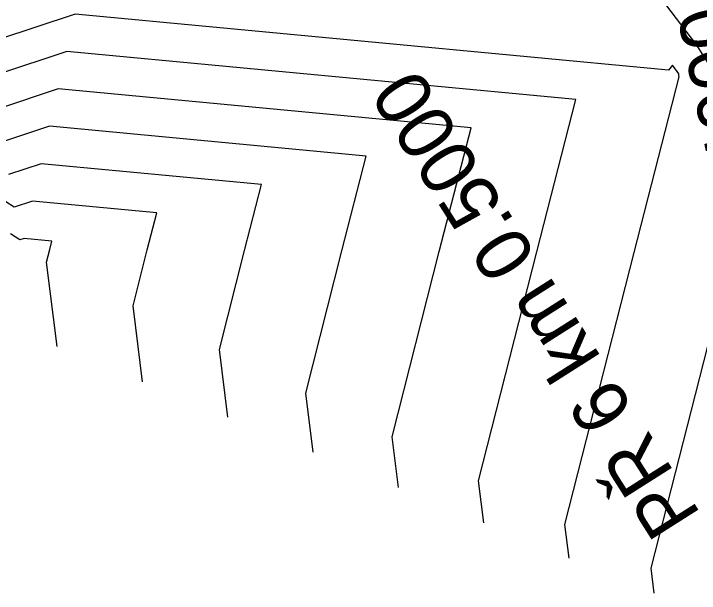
# Model space of a CAD drawing. Extents: x -549394 to -546608, y -1037055 to -1033629.
# Drawn here: x -548066.1 to -547954.3, y -1035778.1 to -1035683.5 of the extents above; entities that cross this region are included whole.
import ezdxf

# ---------------------------------------------------------------- set-up
doc = ezdxf.new("R2010")
doc.units = 0
for name, color, linetype in [('hlavni_vrst', 7, 'Continuous'), ('norm_vrst', 7, 'Continuous'), ('x_popis_pricne_rezy_C11', 7, 'Continuous')]:
    doc.layers.add(name, color=color, linetype=linetype)

msp = doc.modelspace()

# ---------------------------------------------------------------- linework, layer by layer
at = {"layer": 'hlavni_vrst'}
for p, q in [((-548056.05, -1035683.58), (-548070.72, -1035688.47)), ((-547959.3, -1035692.74), (-548056.05, -1035683.58)), ((-547958.65, -1035691.93), (-547959.3, -1035692.74)), ((-547957.89, -1035692.94), (-547958.65, -1035691.93)), ((-547964.92, -1035722.49), (-547957.57, -1035693.82)), ((-547957.63, -1035693.36), (-547957.89, -1035692.94)), ((-547957.61, -1035693.71), (-547957.63, -1035693.36)), ((-547957.57, -1035693.82), (-547957.61, -1035693.71)), ((-548066.01, -1035715.11), (-548072.95, -1035710.68)), ((-548063, -1035714.11), (-548066.01, -1035715.11)), ((-548042.75, -1035716.02), (-548063, -1035714.11)), ((-548044.31, -1035722.08), (-548042.75, -1035716.02)), ((-548046.62, -1035731.19), (-548044.31, -1035722.08)), ((-547976.21, -1035766.87), (-547964.92, -1035722.49)), ((-548045.09, -1035743.59), (-548046.62, -1035731.19)), ((-547975.53, -1035772.36), (-547976.21, -1035766.87))]:
    msp.add_line(p, q, dxfattribs=at)
at = {"layer": 'norm_vrst'}
for p, q in [((-547954.71, -1035688.66), (-547974.52, -1035662.54)), ((-547947.81, -1035699.61), (-547954.71, -1035688.66)), ((-548057.44, -1035689.69), (-548069.78, -1035693.8)), ((-547974.42, -1035697.54), (-548057.44, -1035689.69)), ((-548058.83, -1035695.79), (-548068.83, -1035699.13)), ((-547991.5, -1035702.16), (-548058.83, -1035695.79)), ((-547980.8, -1035722.41), (-547974.42, -1035697.54)), ((-548060.22, -1035701.9), (-548067.89, -1035704.45)), ((-548008.59, -1035706.78), (-548060.22, -1035701.9)), ((-547996.68, -1035722.33), (-547991.5, -1035702.16)), ((-548012.55, -1035722.25), (-548008.59, -1035706.78)), ((-548061.61, -1035708), (-548066.95, -1035709.78)), ((-548025.67, -1035711.4), (-548061.61, -1035708)), ((-548028.43, -1035722.17), (-548025.67, -1035711.4)), ((-548065.06, -1035720.44), (-548066.62, -1035719.44)), ((-548064.39, -1035720.21), (-548065.06, -1035720.44)), ((-548059.84, -1035720.64), (-548064.39, -1035720.21)), ((-548060.19, -1035722), (-548059.84, -1035720.64)), ((-548060.71, -1035724.05), (-548060.19, -1035722)), ((-548032.54, -1035738.32), (-548028.43, -1035722.17)), ((-548018.46, -1035745.46), (-548012.55, -1035722.25)), ((-548004.37, -1035752.6), (-547996.68, -1035722.33)), ((-547990.29, -1035759.74), (-547980.8, -1035722.41)), ((-547962.13, -1035774.01), (-547949.04, -1035722.57)), ((-548059, -1035737.84), (-548060.71, -1035724.05)), ((-548031.18, -1035749.35), (-548032.54, -1035738.32)), ((-548017.26, -1035755.1), (-548018.46, -1035745.46)), ((-548003.35, -1035760.85), (-548004.37, -1035752.6)), ((-547989.44, -1035766.61), (-547990.29, -1035759.74)), ((-547961.62, -1035778.12), (-547962.13, -1035774.01))]:
    msp.add_line(p, q, dxfattribs=at)

# ---------------------------------------------------------------- texts
at = {"layer": 'x_popis_pricne_rezy_C11'}
for s, rotation, p in [('PŘ 5 km 0.4000', 101.8343, (-547931.24, -1035766.69)), ('PŘ 6 km 0.5000', 122.4137, (-547953.9, -1035765.31))]:
    msp.add_text(s, height=9.0627, rotation=rotation, dxfattribs=at).set_placement(p)

doc.saveas('drawing.dxf')
